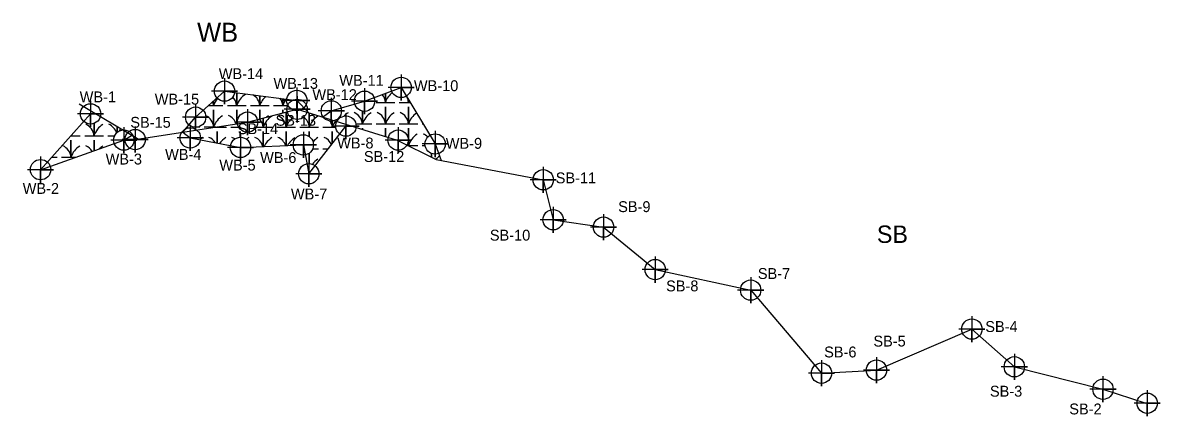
# Model space of a CAD drawing. Extents: x 1581951 to 1583895, y 930673 to 932553.
# Drawn here: x 1582230.3 to 1582491.9, y 931967.8 to 932058.3 of the extents above; entities that cross this region are included whole.
import ezdxf

# ---------------------------------------------------------------- set-up
doc = ezdxf.new("R2010")
doc.units = 0
for name, color, linetype in [('Exist Environmental Wetland Boundary', 7, 'Continuous'), ('Exist Environmental Wetland Boundary Cogo Comment', 7, 'Continuous'), ('Exist Environmental Wetland Boundary Cogo Point CELL', 7, 'Continuous'), ('Exist Hydro Jurisdictional Stream or Body of Water NEU Mitigable', 7, 'Continuous'), ('Exist Hydro Jurisdictional Stream or Body of Water NEU Mitigable Cogo Comment', 7, 'Continuous'), ('Exist Hydro Jurisdictional Stream or Body of Water NEU Mitigable Cogo Point CELL', 7, 'Continuous')]:
    doc.layers.add(name, color=color, linetype=linetype)

msp = doc.modelspace()

# ---------------------------------------------------------------- linework, layer by layer
at = {"layer": 'Exist Environmental Wetland Boundary'}
for p, q in [((1582303.1, 932036.35), (1582303.1, 932036.6)), ((1582303.1, 932036.6), (1582303.1, 932036.35)), ((1582251.99, 932033.1), (1582251.99, 932034.4)), ((1582251.99, 932034.4), (1582251.99, 932033.1)), ((1582270.66, 932034.36), (1582271.05, 932034.36)), ((1582278.14, 932034.31), (1582279.96, 932034.31)), ((1582322.15, 932035.07), (1582322.35, 932035.07)), ((1582241.41, 932032.36), (1582243.54, 932032.36)), ((1582249.84, 932032.36), (1582251.43, 932032.36)), ((1582297, 932029.36), (1582298.34, 932029.36)), ((1582299.34, 932029.36), (1582300.57, 932029.36)), ((1582322.15, 932030.13), (1582322.82, 932030.13)), ((1582236.98, 932027.42), (1582238.24, 932027.42)), ((1582296.19, 932025.95), (1582296.19, 932028.33)), ((1582296.19, 932028.33), (1582296.19, 932025.95)), ((1582324.3, 932027.43), (1582324.3, 932028.26)), ((1582324.3, 932028.26), (1582324.3, 932027.43))]:
    msp.add_line(p, q, dxfattribs=at)
for points in [[(1582267.08, 932033.15), (1582270.06, 932036.62), (1582276.71, 932042.6), (1582293.33, 932040.47), (1582296, 932037.7)], [(1582277.35, 932039.3), (1582279.5, 932039.3), (1582279.5, 932042.24)], [(1582279.5, 932042.24), (1582279.5, 932039.3), (1582281.65, 932039.3)], [(1582299.22, 932036.65), (1582301.26, 932038.05), (1582308.92, 932040.29), (1582317.31, 932043.46), (1582325.14, 932030.45), (1582326.55, 932026.68)], [(1582311.55, 932040.02), (1582313.7, 932040.02), (1582313.7, 932042.1)], [(1582313.7, 932042.1), (1582313.7, 932040.02), (1582315.85, 932040.02)], [(1582273.04, 932039.3), (1582274.2, 932039.3), (1582274.2, 932040.35)], [(1582274.2, 932040.35), (1582274.2, 932039.3), (1582276.35, 932039.3)], [(1582282.65, 932039.3), (1582284.8, 932039.3), (1582284.8, 932041.57)], [(1582284.8, 932041.57), (1582284.8, 932039.3), (1582286.95, 932039.3)], [(1582287.95, 932039.3), (1582290.1, 932039.3), (1582290.1, 932040.89)], [(1582290.1, 932040.89), (1582290.1, 932039.3), (1582291.22, 932039.3)], [(1582316.85, 932040.02), (1582319, 932040.02), (1582319, 932040.64)], [(1582319, 932040.64), (1582319, 932040.02), (1582319.38, 932040.02)], [(1582245.9, 932037.38), (1582234.4, 932024.54), (1582253.54, 932031.35), (1582255.34, 932032.42)], [(1582272.05, 932034.36), (1582274.2, 932034.36), (1582274.2, 932038.3), (1582274.2, 932034.36), (1582274.75, 932034.36)], [(1582279.5, 932035.1), (1582279.5, 932038.3), (1582279.5, 932035.1)], [(1582284.8, 932036.21), (1582284.8, 932038.3), (1582284.8, 932036.21)], [(1582288.74, 932034.31), (1582290.89, 932034.31), (1582290.89, 932037.78)], [(1582290.1, 932037.57), (1582290.1, 932038.3), (1582290.1, 932037.57)], [(1582290.89, 932037.78), (1582290.89, 932034.31), (1582293.04, 932034.31)], [(1582294.04, 932034.31), (1582296.19, 932034.31), (1582296.19, 932037.56)], [(1582296.19, 932037.56), (1582296.19, 932034.31), (1582298.34, 932034.31)], [(1582306.92, 932035.07), (1582308.4, 932035.07), (1582308.4, 932038)], [(1582308.4, 932038), (1582308.4, 932035.07), (1582310.55, 932035.07)], [(1582311.55, 932035.07), (1582313.7, 932035.07), (1582313.7, 932039.02), (1582313.7, 932035.07), (1582315.85, 932035.07)], [(1582316.85, 932035.07), (1582319, 932035.07), (1582319, 932039.02), (1582319, 932035.07), (1582321.15, 932035.07)], [(1582244.54, 932032.36), (1582246.69, 932032.36), (1582246.69, 932035.17)], [(1582246.69, 932035.17), (1582246.69, 932032.36), (1582248.84, 932032.36)], [(1582267.08, 932033.14), (1582268.83, 932031.85), (1582280.37, 932029.66), (1582294.83, 932030.24), (1582296.08, 932023.61), (1582304.63, 932034.57), (1582304.87, 932034.88)], [(1582274.44, 932034.31), (1582274.99, 932034.31), (1582274.99, 932034.39)], [(1582274.99, 932034.39), (1582274.99, 932034.31), (1582277.14, 932034.31)], [(1582284.01, 932034.31), (1582285.59, 932034.31), (1582285.59, 932036.41)], [(1582285.59, 932036.41), (1582285.59, 932034.31), (1582287.74, 932034.31)], [(1582299.34, 932034.31), (1582301.49, 932034.31), (1582301.49, 932035.72)], [(1582301.49, 932035.72), (1582301.49, 932034.31), (1582302.3, 932034.31)], [(1582308.4, 932033.79), (1582308.4, 932034.07), (1582308.4, 932033.79)], [(1582313.7, 932032.16), (1582313.7, 932034.07), (1582313.7, 932032.16)], [(1582318.84, 932030.13), (1582319, 932030.13), (1582319, 932034.07), (1582319, 932030.13), (1582321.15, 932030.13)], [(1582239.24, 932027.42), (1582241.39, 932027.42), (1582241.39, 932031.36), (1582241.39, 932027.42), (1582242.49, 932027.42)], [(1582246.69, 932028.91), (1582246.69, 932031.36), (1582246.69, 932028.91)], [(1582274.99, 932030.68), (1582274.99, 932033.31), (1582274.99, 932030.68)], [(1582280.29, 932032), (1582280.29, 932033.31), (1582280.29, 932032)], [(1582285.59, 932029.87), (1582285.59, 932033.31), (1582285.59, 932029.87)], [(1582290.89, 932030.08), (1582290.89, 932033.31), (1582290.89, 932030.08)], [(1582296.19, 932032.16), (1582296.19, 932033.31), (1582296.19, 932032.16)], [(1582301.49, 932030.55), (1582301.49, 932033.31), (1582301.49, 932030.55)], [(1582236.09, 932026.16), (1582236.09, 932026.42), (1582236.09, 932026.16)]]:
    msp.add_lwpolyline(points, dxfattribs=at)
for centre, radius, start, end in [((1582284.06, 932037.79), 4.81, 122.1274, 161.6222), ((1582281.73, 932039.08), 3.07, 4.1403, 60.904), ((1582310.64, 932039.79), 3.07, 4.1403, 41.0615), ((1582318.26, 932038.5), 4.81, 128.2812, 161.6222), ((1582271.13, 932039.08), 3.07, 4.1403, 20.8263), ((1582278.76, 932037.79), 4.81, 139.6608, 161.6222), ((1582276.43, 932039.08), 3.07, 4.1403, 44.7634), ((1582289.36, 932037.79), 4.81, 131.4494, 161.6222), ((1582287.03, 932039.08), 3.07, 4.1403, 37.9064), ((1582294.66, 932037.79), 4.81, 141.4149, 161.6222), ((1582315.94, 932039.79), 3.07, 4.1403, 26.3261), ((1582323.56, 932038.5), 4.81, 156.7353, 161.6222), ((1582271.13, 932034.14), 3.07, 4.1403, 66.0625), ((1582278.76, 932032.84), 4.81, 122.1274, 161.6222), ((1582276.43, 932034.14), 3.07, 17.8012, 67.535), ((1582290.15, 932032.79), 4.81, 122.1274, 161.6222), ((1582289.36, 932032.84), 4.81, 122.1274, 128.2071), ((1582287.82, 932034.09), 3.07, 4.1403, 67.535), ((1582293.12, 932034.09), 3.07, 4.1403, 55.1881), ((1582300.75, 932032.79), 4.81, 122.1274, 161.6222), ((1582307.66, 932033.56), 4.81, 122.1274, 136.3267), ((1582305.33, 932034.85), 3.07, 4.1403, 67.535), ((1582312.96, 932033.56), 4.81, 122.1274, 161.6222), ((1582310.64, 932034.85), 3.07, 4.1403, 67.535), ((1582318.26, 932033.56), 4.81, 122.1274, 161.6222), ((1582315.94, 932034.85), 3.07, 4.1403, 67.535), ((1582323.56, 932033.56), 4.81, 124.0701, 161.6222), ((1582243.62, 932032.14), 3.07, 4.1403, 67.535), ((1582251.25, 932030.85), 4.81, 122.1274, 161.6222), ((1582248.92, 932032.14), 3.07, 16.1944, 67.535), ((1582256.55, 932030.85), 4.81, 140.6275, 147.1238), ((1582271.92, 932034.09), 3.07, 4.1403, 5.7017), ((1582279.55, 932032.79), 4.81, 160.4956, 161.6222), ((1582282.52, 932034.09), 3.07, 4.1403, 43.3586), ((1582295.45, 932032.79), 4.81, 131.8137, 161.6222), ((1582298.42, 932034.09), 3.07, 4.1403, 32.0317), ((1582306.05, 932032.79), 4.81, 142.8125, 161.6222), ((1582300.03, 932034.85), 3.07, 23.8783, 27.289), ((1582274.25, 932027.85), 4.81, 122.1274, 130.066), ((1582271.92, 932029.14), 3.07, 31.9291, 67.535), ((1582279.55, 932027.85), 4.81, 122.1274, 145.5458), ((1582277.22, 932029.14), 3.07, 53.1856, 67.535), ((1582284.85, 932027.85), 4.81, 122.1274, 129.8303), ((1582282.52, 932029.14), 3.07, 13.6371, 67.535), ((1582290.15, 932027.85), 4.81, 122.1274, 155.0186), ((1582287.82, 932029.14), 3.07, 17.7548, 67.535), ((1582295.45, 932027.85), 4.81, 122.1274, 152.0951), ((1582300.75, 932027.85), 4.81, 122.1274, 139.9727), ((1582298.42, 932029.14), 3.07, 21.6719, 67.535), ((1582310.64, 932029.9), 3.07, 67.2985, 67.535), ((1582323.56, 932028.61), 4.81, 122.1274, 161.6222), ((1582321.24, 932029.9), 3.07, 44.4316, 67.535), ((1582238.32, 932027.19), 3.07, 4.1403, 67.535), ((1582245.95, 932025.9), 4.81, 122.1274, 161.6222), ((1582243.62, 932027.19), 3.07, 30.6355, 67.535), ((1582251.25, 932025.9), 4.81, 122.1274, 134.334), ((1582315.94, 932029.9), 3.07, 4.1403, 16.5448), ((1582300.75, 932022.9), 4.81, 122.1274, 142.9636), ((1582328.86, 932023.67), 4.81, 123.9203, 137.2518), ((1582293.12, 932024.2), 3.07, 33.9647, 35.0854)]:
    msp.add_arc(centre, radius, start, end, dxfattribs=at)
at = {"layer": 'Exist Environmental Wetland Boundary Cogo Point CELL'}
for points in [[(1582276.71, 932045.6), (1582276.71, 932039.6), (1582276.71, 932042.6), (1582279.71, 932042.6), (1582273.71, 932042.6)], [(1582317.31, 932046.46), (1582317.31, 932040.46), (1582317.31, 932043.46), (1582320.31, 932043.46), (1582314.31, 932043.46)], [(1582293.33, 932043.47), (1582293.33, 932037.47), (1582293.33, 932040.47), (1582296.33, 932040.47), (1582290.33, 932040.47)], [(1582308.92, 932043.29), (1582308.92, 932037.29), (1582308.92, 932040.29), (1582311.92, 932040.29), (1582305.92, 932040.29)], [(1582245.9, 932040.38), (1582245.9, 932034.38), (1582245.9, 932037.38), (1582248.9, 932037.38), (1582242.9, 932037.38)], [(1582270.06, 932039.62), (1582270.06, 932033.62), (1582270.06, 932036.62), (1582273.06, 932036.62), (1582267.06, 932036.62)], [(1582301.26, 932041.05), (1582301.26, 932035.05), (1582301.26, 932038.05), (1582304.26, 932038.05), (1582298.26, 932038.05)], [(1582304.63, 932037.57), (1582304.63, 932031.57), (1582304.63, 932034.57), (1582307.63, 932034.57), (1582301.63, 932034.57)], [(1582253.54, 932034.35), (1582253.54, 932028.35), (1582253.54, 932031.35), (1582256.54, 932031.35), (1582250.54, 932031.35)], [(1582268.83, 932034.85), (1582268.83, 932028.85), (1582268.83, 932031.85), (1582271.83, 932031.85), (1582265.83, 932031.85)], [(1582280.37, 932032.66), (1582280.37, 932026.66), (1582280.37, 932029.66), (1582283.37, 932029.66), (1582277.37, 932029.66)], [(1582294.83, 932033.24), (1582294.83, 932027.24), (1582294.83, 932030.24), (1582297.83, 932030.24), (1582291.83, 932030.24)], [(1582325.14, 932033.45), (1582325.14, 932027.45), (1582325.14, 932030.45), (1582328.14, 932030.45), (1582322.14, 932030.45)], [(1582234.4, 932027.54), (1582234.4, 932021.54), (1582234.4, 932024.54), (1582237.4, 932024.54), (1582231.4, 932024.54)], [(1582296.08, 932026.61), (1582296.08, 932020.61), (1582296.08, 932023.61), (1582299.08, 932023.61), (1582293.08, 932023.61)]]:
    msp.add_lwpolyline(points, dxfattribs=at)
for centre in [(1582276.71, 932042.6), (1582317.31, 932043.46), (1582293.33, 932040.47), (1582308.92, 932040.29), (1582245.9, 932037.38), (1582301.26, 932038.05), (1582270.06, 932036.62), (1582304.63, 932034.57), (1582268.83, 932031.85), (1582253.54, 932031.35), (1582280.37, 932029.66), (1582294.83, 932030.24), (1582325.14, 932030.45), (1582234.4, 932024.54), (1582296.08, 932023.61)]:
    msp.add_circle(centre, 2.34, dxfattribs=at)
at = {"layer": 'Exist Hydro Jurisdictional Stream or Body of Water NEU Mitigable'}
msp.add_line((1582257.04, 932031.39), (1582243.27, 932039.6), dxfattribs=at)
msp.add_lwpolyline([(1582256.16, 932031.46), (1582281.99, 932035.48), (1582293.39, 932038.42), (1582316.37, 932031.34), (1582325.4, 932026.89), (1582350, 932022.21), (1582352.27, 932013.03), (1582363.84, 932011.33), (1582375.75, 932001.56), (1582397.7, 931996.85), (1582413.99, 931977.75), (1582426.63, 931978.46), (1582448.58, 931987.89), (1582458.34, 931979.21), (1582478.72, 931974.05), (1582488.55, 931970.84)], dxfattribs=at)
at = {"layer": 'Exist Hydro Jurisdictional Stream or Body of Water NEU Mitigable Cogo Point CELL'}
for points in [[(1582293.39, 932041.42), (1582293.39, 932035.42), (1582293.39, 932038.42), (1582296.39, 932038.42), (1582290.39, 932038.42)], [(1582281.99, 932038.48), (1582281.99, 932032.48), (1582281.99, 932035.48), (1582284.99, 932035.48), (1582278.99, 932035.48)], [(1582256.16, 932034.46), (1582256.16, 932028.46), (1582256.16, 932031.46), (1582259.16, 932031.46), (1582253.16, 932031.46)], [(1582316.61, 932034.34), (1582316.61, 932028.34), (1582316.61, 932031.34), (1582319.61, 932031.34), (1582313.61, 932031.34)], [(1582350, 932025.21), (1582350, 932019.21), (1582350, 932022.21), (1582353, 932022.21), (1582347, 932022.21)], [(1582352.27, 932016.03), (1582352.27, 932010.03), (1582352.27, 932013.03), (1582355.27, 932013.03), (1582349.27, 932013.03)], [(1582363.88, 932014.33), (1582363.88, 932008.33), (1582363.88, 932011.33), (1582366.88, 932011.33), (1582360.88, 932011.33)], [(1582375.75, 932004.56), (1582375.75, 931998.56), (1582375.75, 932001.56), (1582378.75, 932001.56), (1582372.75, 932001.56)], [(1582397.7, 931999.85), (1582397.7, 931993.85), (1582397.7, 931996.85), (1582400.7, 931996.85), (1582394.7, 931996.85)], [(1582448.58, 931990.89), (1582448.58, 931984.89), (1582448.58, 931987.89), (1582451.58, 931987.89), (1582445.58, 931987.89)], [(1582458.34, 931982.21), (1582458.34, 931976.21), (1582458.34, 931979.21), (1582461.34, 931979.21), (1582455.34, 931979.21)], [(1582413.99, 931980.75), (1582413.99, 931974.75), (1582413.99, 931977.75), (1582416.99, 931977.75), (1582410.99, 931977.75)], [(1582426.63, 931981.46), (1582426.63, 931975.46), (1582426.63, 931978.46), (1582429.63, 931978.46), (1582423.63, 931978.46)], [(1582478.72, 931977.05), (1582478.72, 931971.05), (1582478.72, 931974.05), (1582481.72, 931974.05), (1582475.72, 931974.05)], [(1582488.89, 931973.84), (1582488.89, 931967.84), (1582488.89, 931970.84), (1582491.89, 931970.84), (1582485.89, 931970.84)]]:
    msp.add_lwpolyline(points, dxfattribs=at)
for centre in [(1582293.39, 932038.42), (1582281.99, 932035.48), (1582256.16, 932031.46), (1582316.61, 932031.34), (1582350, 932022.21), (1582352.27, 932013.03), (1582363.88, 932011.33), (1582375.75, 932001.56), (1582397.7, 931996.85), (1582448.58, 931987.89), (1582458.34, 931979.21), (1582413.99, 931977.75), (1582426.63, 931978.46), (1582478.72, 931974.05), (1582488.89, 931970.84)]:
    msp.add_circle(centre, 2.34, dxfattribs=at)

# ---------------------------------------------------------------- texts
at = {"layer": 'Exist Environmental Wetland Boundary Cogo Comment'}
for s, height, p in [('WB', 4.375, (1582270.4, 932053.95)), ('WB-14', 2.5, (1582275.38, 932045.36)), ('WB-13', 2.5, (1582287.97, 932043.13)), ('WB-11', 2.5, (1582303.09, 932043.83)), ('WB-10', 2.5, (1582320.25, 932042.6)), ('WB-1', 2.5, (1582243.39, 932040.03)), ('WB-15', 2.5, (1582260.65, 932039.51)), ('WB-12', 2.5, (1582296.91, 932040.55)), ('WB-8', 2.5, (1582302.61, 932029.42)), ('WB-9', 2.5, (1582327.58, 932029.35)), ('WB-4', 2.5, (1582263.04, 932026.8)), ('WB-6', 2.5, (1582284.88, 932026.08)), ('WB-3', 2.5, (1582249.36, 932025.73)), ('WB-5', 2.5, (1582275.5, 932024.34)), ('WB-2', 2.5, (1582230.29, 932018.98)), ('WB-7', 2.5, (1582291.97, 932017.7))]:
    msp.add_text(s, height=height, dxfattribs=at).set_placement(p)
at = {"layer": 'Exist Hydro Jurisdictional Stream or Body of Water NEU Mitigable Cogo Comment'}
for s, height, p in [('SB-15', 2.5, (1582255.04, 932034.18)), ('SB-13', 2.5, (1582288.45, 932034.65)), ('SB-14', 2.5, (1582279.75, 932032.71)), ('SB-12', 2.5, (1582308.75, 932026.32)), ('SB-11', 2.5, (1582352.87, 932021.4)), ('SB-9', 2.5, (1582367.23, 932014.79)), ('SB-10', 2.5, (1582337.72, 932008.23)), ('SB', 4, (1582426.73, 932007.7)), ('SB-7', 2.5, (1582399.35, 931999.41)), ('SB-8', 2.5, (1582378.25, 931996.56)), ('SB-4', 2.5, (1582451.65, 931987.22)), ('SB-5', 2.5, (1582425.92, 931983.87)), ('SB-6', 2.5, (1582414.6, 931981.37)), ('SB-3', 2.5, (1582452.72, 931972.35)), ('SB-2', 2.5, (1582470.97, 931968.27))]:
    msp.add_text(s, height=height, dxfattribs=at).set_placement(p)

doc.saveas('drawing.dxf')
